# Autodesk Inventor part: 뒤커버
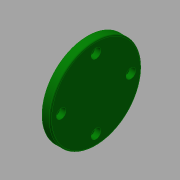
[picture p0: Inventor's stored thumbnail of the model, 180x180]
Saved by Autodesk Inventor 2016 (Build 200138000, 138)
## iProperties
Created: 2015-09
Part Number: 뒤커버
Material: 알루미늄 6061
Document SubType Name: Modeling
Designer: mduedu
Density: 2.71 g/cm^3
Mass: 54.0417 g
Surface Area: 84.9688 cm^2
Volume: 19.9416 cm^3
Appearance: 진녹색
Author: mduedu
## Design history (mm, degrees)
sketch "스케치1"
  geometry: L1 (-15.5, 47)-(-15.5, 85); L2 (-15.5, 85)-(-22.5, 85); L3 (-22.5, 85)-(-22.5, 67); L4 (-25.5, 67)-(-25.5, 47); L5 (-79.5, 39.5)-(-79.5, 54.5) reference; L6 (48.5, 54.5)-(48.5, 39.5) reference; L7 (-79.5, 47)-(48.5, 47); L8 (-22.5, 67)-(-25.5, 67); L9 (-25.5, 47)-(-15.5, 47); 1 further point
  constraints: 14 end point, 4 midpoint, 3 parallel, 1 collinear, 1 point on line, 1 vertical
  dimensions: "d6" = 76 diameter of L2 L7; "d7" = 7 distance of L1.end L2.end; "d8" = 40 diameter of L3.end L7; "d32" = 10 distance between parallel lines of L1 L4
revolve "회전1" sketch "스케치1" stored, may be unused: angle "d4" = 90 deg
sketch "스케치4"
  geometry: C1 r 38 at (0, 0) reference; 2 further points
  constraints: 1 coincident
hole "구멍3" sketch "스케치4" at (0, 0) diameter "d33" = 33; stored, may be unused: countersink angle "d37" = 90 deg, drill point angle "d39" = 0 deg; dims "d34" = 6, "d35" = 4, "d36" = 2, "d38" = 5
fillet "모깎기4" dims "d40" = 1
chamfer "모따기2" distance "d41" = 1; stored, may be unused: second distance "d42" = 2, angle "d43" = 45 deg
sketch "스케치6" dims "d56" = 58
  geometry: C1 r 38 at (0, 0) reference; 5 further points
  constraints: 2 vertical alignment, 1 coincident, 7 other
  dimensions: "d59" = 360 deg dimension on C1.centre point (0, 29) (derived)
sketch "스케치7"
  geometry: 4 further points
  constraints: 4 other
hole "구멍5" sketch "스케치7" at (0, 29), (-29, 0), (29, 0), (0, -29) diameter "d62" = 4.5; stored, may be unused: countersink angle "d66" = 90 deg, drill point angle "d68" = 0 deg; dims "d63" = 6, "d64" = 8, "d65" = 4.6, "d67" = 8
node "솔리드1"
node "참조1"
node "참조2"
